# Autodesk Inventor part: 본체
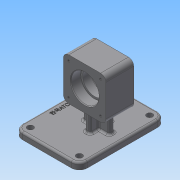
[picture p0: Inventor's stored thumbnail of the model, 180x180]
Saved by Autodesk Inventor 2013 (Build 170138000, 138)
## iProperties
Created: 2020-11
Part Number: 본체
Material: Generic
Document SubType Name: Modeling
Designer: Administrator
Density: 1 g/cm^3
Author: Administrator
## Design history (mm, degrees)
sketch "스케치1"
  geometry: L1 (65, -49)-(-65, -49); L2 (-65, -49)-(-65, 49); L3 (-65, 49)-(65, 49); L4 (65, 49)-(65, -49); L5 (65, -49)-(-65, 49); L6 (-65, -49)-(65, 49); 1 further point
  constraints: 12 end point, 2 midpoint, 2 parallel, 1 horizontal, 1 perpendicular
  dimensions: "d0" = 130 distance of L2.end L3.end; "d2" = 98 distance between parallel lines of L3 L1
extrude "돌출1" new body sketch "스케치1" distance "d3" = 10; taper "d4" = 0 deg
fillet "모깎기1" dims "d5" = 12
node "작업 평면2"
sketch "스케치3"
  geometry: L1 (21, 70)-(85, 70); L2 (0, 0)-(106, 0) reference; L3 (74, 38)-(32, 38); L4 (32, 38)-(32, 102); L5 (32, 102)-(74, 102); L6 (74, 102)-(74, 38); L7 (74, 38)-(32, 102); L8 (32, 38)-(74, 102); 3 further points
  constraints: 14 end point, 4 midpoint, 2 horizontal, 2 parallel, 1 perpendicular, 1 vertical alignment
  dimensions: "d9" = 70 distance between parallel lines of L2 L1; "d10" = 64 distance of L1.start L1.end; "d13" = 64 distance between parallel lines of L3 L5; "d14" = 42 distance between parallel lines of L6 L4
extrude "돌출2" join sketch "스케치3" stored distance "d15" = 64; taper "d16" = 0 deg
node "작업 평면3"
sketch "스케치6"
  geometry: L1 (-38, -8)-(-38, 56) reference; L2 (-10, -12)-(-10, 0) reference; L3 (-10, 74)-(-10, 0) reference; L4 (-38, 24)-(-10, 24); L5 (-10, 24)-(-10, 4); L6 (-10, 24)-(-10, 44); L7 (-10, 44)-(-40.592, 44); L8 (-40.592, 44)-(-40.592, 4); L9 (-10, 4)-(-40.592, 4); 1 further point
  constraints: 12 end point, 3 perpendicular, 3 point on line, 1 midpoint, 1 parallel
  dimensions: "d18" = 20 distance of L4.end L5.end; "d19" = 20 distance of L4.end L6.end; "d20" = 30.59241 distance of L8.end L5.end
extrude "돌출3" join sketch "스케치6" stored distance "d22" = 8; taper "d23" = 0 deg
node "작업 평면4"
node "작업 평면5"
sketch "스케치7"
  geometry: L1 (32, 102)-(74, 102) reference; L2 (74, 38)-(32, 38) reference; L3 (106, 10)-(0, 10) reference; L4 (36, 10)-(70, 10); L5 (36, 10)-(36, 39.712); L6 (70, 10)-(70, 39.712); L7 (70, 39.712)-(36, 39.712); 3 further points
  constraints: 8 end point, 2 midpoint, 2 perpendicular, 2 point on line, 1 vertical alignment
  dimensions: "d24" = 34 distance of L4.start L4.end; "d109" = 34 distance of L6.end L5.end; "d110" = 29.71183 distance of L4.end L6.end
extrude "돌출4" join sketch "스케치7" stored distance "d27" = 8; taper "d28" = 0 deg
sketch "스케치8"
  geometry: L1 (0, 0)-(0, 64) reference; L2 (64, 0)-(0, 0) reference; L3 (64, 64)-(64, 0) reference; L4 (0, 64)-(64, 64) reference; L5 (0, 64)-(64, 64) reference; C1 r 21 at (32, 32); 4 further points
  constraints: 3 midpoint, 1 centre point, 1 horizontal alignment, 1 vertical alignment
  dimensions: "d29" = 42 diameter of C1
extrude "돌출5" cut sketch "스케치8" distance "d31" = 15; taper "d32" = 0 deg
sketch "스케치9"
  geometry: C1 r 21 at (0, 0) reference; C2 r 18 at (0, 0); 1 further point
  constraints: 1 centre point, 1 coincident
  dimensions: "d33" = 36 diameter of C2
extrude "돌출6" cut sketch "스케치9" distance "d36" = 12; taper "d37" = 0 deg
sketch "스케치10"
  geometry: C1 r 18 at (32, 32) reference; C2 r 21 at (32, 32); 1 further point
  constraints: 1 centre point, 1 coincident
  dimensions: "d38" = 42 diameter of C2
extrude "돌출7" cut sketch "스케치10" distance "d40" = 15; taper "d41" = 0 deg
fillet "모깎기2" dims "d42" = 0.3
chamfer "모따기1" distance "d43" = 1; stored, may be unused: second distance "d44" = 2, angle "d45" = 45 deg
fillet "모깎기3" dims "d46" = 3
sketch "스케치11"
  geometry: L1 (0, 0)-(0, 64) reference; L2 (64, 0)-(0, 0) reference; L3 (64, 0)-(64, 64) reference; L4 (0, 64)-(64, 64) reference; C1 r 22 at (32, 32) reference; 5 further points
  dimensions: "d47" = 24 horizontal distance of C1.centre point (56, 56); "d48" = 24 horizontal distance of C1.centre point (56, 56); "d49" = 48 distance of point (8, 56) point (56, 56); "d50" = 24 horizontal distance of C1.centre point (8, 56); "d51" = 48 distance of point (8, 56) point (8, 8); "d52" = 24 horizontal distance of C1.centre point (8, 8); "d53" = 48 distance of point (56, 8) point (8, 8); "d54" = 24 horizontal distance of point (56, 8) C1.centre
hole "구멍1" sketch "스케치11" at (56, 56), (56, 8), (8, 56), (8, 8) diameter "d55" = 3.242; stored, may be unused: countersink angle "d59" = 90 deg, drill point angle "d61" = 118 deg; dims "d56" = 8, "d57" = 4, "d58" = 2, "d60" = 10
node "작업 평면6"
hole "구멍2" diameter "d64" = 9; stored, may be unused: countersink angle "d68" = 90 deg, drill point angle "d70" = 0 deg; dims "d62" = 10, "d63" = 10, "d65" = 8, "d66" = 4, "d67" = 2, "d69" = 10
hole "구멍3" diameter "d73" = 9; stored, may be unused: countersink angle "d77" = 90 deg, drill point angle "d79" = 0 deg; dims "d71" = 10, "d72" = 10, "d74" = 8, "d75" = 4, "d76" = 2, "d78" = 10
hole "구멍4" diameter "d82" = 9; stored, may be unused: countersink angle "d86" = 90 deg, drill point angle "d88" = 0 deg; dims "d80" = 10, "d81" = 10, "d83" = 8, "d84" = 4, "d85" = 2, "d87" = 10
hole "구멍5" diameter "d91" = 9; stored, may be unused: countersink angle "d95" = 90 deg, drill point angle "d97" = 0 deg; dims "d89" = 10, "d90" = 10, "d92" = 8, "d93" = 4, "d94" = 2, "d96" = 10
fillet "모깎기5" dims "d99" = 3
fillet "모깎기8" dims "d102" = 8
sketch "스케치12"
  geometry: L1 (53, 49)-(-53, 49) reference; L2 (65, -37)-(65, 37) reference; 2 further points
  constraints: 1 other
  dimensions: "d103" = 10 distance from line of point (0, 39) L1; "d104" = 65 distance from line of point (0, 39) L2
feature "엠보싱1" sketch "스케치12" dims "d0" = 130, "d2" = 98, "d9" = 70, "d10" = 64, "d13" = 64, "d14" = 42, "d105" = 0.5, "d106" = 0
fillet "모깎기11" dims "d111" = 3
fillet "모깎기12" dims "d112" = 3
node "솔리드1"
mirror "대칭1"
node "투영된 루프1"
node "투영된 루프2"
node "투영된 루프3"
other parameters: "d7" = -62, "d17" = -65
